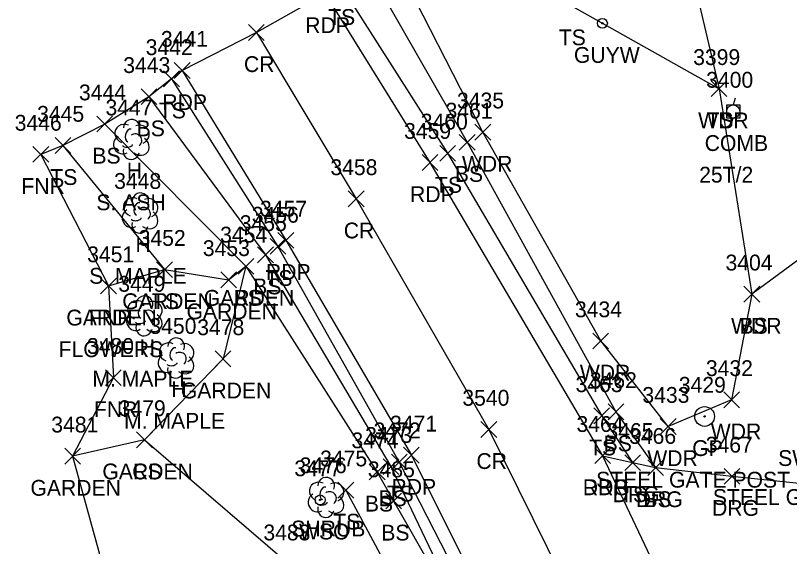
# Model space of a CAD drawing. Extents: x 1461855 to 1464118, y 556196 to 557441.
# Drawn here: x 1461854.8 to 1461952.7, y 556656.2 to 556723.3 of the extents above; entities that cross this region are included whole.
import ezdxf

# ---------------------------------------------------------------- set-up
doc = ezdxf.new("R2010")
doc.units = 0
for name, color, linetype in [('L_A', 7, 'Continuous'), ('L_C', 7, 'Continuous'), ('L_I', 7, 'Continuous'), ('L_TIC', 7, 'Continuous'), ('LAPB', 7, 'Continuous'), ('LAWA', 7, 'Continuous'), ('LELB', 7, 'Continuous'), ('LFNC', 7, 'Continuous'), ('LSH', 7, 'Continuous'), ('LSOGP', 7, 'Continuous'), ('LTD', 7, 'Continuous'), ('P_A', 7, 'Continuous'), ('P_I', 7, 'Continuous'), ('P_TIC', 7, 'Continuous'), ('PET', 7, 'Continuous'), ('PRC', 7, 'Continuous'), ('R_A', 7, 'Continuous'), ('R_C', 7, 'Continuous'), ('R_I', 7, 'Continuous'), ('R_TIC', 7, 'Continuous'), ('RDG', 7, 'Continuous'), ('RGP', 7, 'Continuous'), ('U_A', 7, 'Continuous'), ('U_C', 7, 'Continuous'), ('U_I', 7, 'Continuous'), ('UP', 7, 'Continuous'), ('UPGW', 7, 'Continuous'), ('UWV', 7, 'Continuous')]:
    doc.layers.add(name, color=color, linetype=linetype)

msp = doc.modelspace()

# ---------------------------------------------------------------- linework, layer by layer
at = {"layer": 'L_TIC'}
for points in [[(1461873.548, 556714.325), (1461875.548, 556716.325)], [(1461875.548, 556714.325), (1461873.548, 556716.325)], [(1461942.815, 556713.07), (1461944.815, 556715.07)], [(1461944.815, 556713.07), (1461942.815, 556715.07)], [(1461942.815, 556713.07), (1461944.815, 556715.07)], [(1461944.815, 556713.07), (1461942.815, 556715.07)], [(1461870.708, 556712.061), (1461872.708, 556714.061)], [(1461872.708, 556712.061), (1461870.708, 556714.061)], [(1461865.11, 556708.605), (1461867.11, 556710.605)], [(1461867.11, 556708.605), (1461865.11, 556710.605)], [(1461912.933, 556707.582), (1461914.933, 556709.582)], [(1461914.933, 556707.582), (1461912.933, 556709.582)], [(1461859.82, 556705.9), (1461861.82, 556707.9)], [(1461861.82, 556705.9), (1461859.82, 556707.9)], [(1461910.96, 556706.296), (1461912.96, 556708.296)], [(1461912.96, 556706.296), (1461910.96, 556708.296)], [(1461908.481, 556704.911), (1461910.481, 556706.911)], [(1461910.481, 556704.911), (1461908.481, 556706.911)], [(1461857.034, 556704.764), (1461859.034, 556706.764)], [(1461859.034, 556704.764), (1461857.034, 556706.764)], [(1461887.028, 556693.129), (1461889.028, 556695.129)], [(1461889.028, 556693.129), (1461887.028, 556695.129)], [(1461885.45, 556692.067), (1461887.45, 556694.067)], [(1461887.45, 556692.067), (1461885.45, 556694.067)], [(1461882.97, 556690.62), (1461884.97, 556692.62)], [(1461884.97, 556690.62), (1461882.97, 556692.62)], [(1461882.97, 556690.62), (1461884.97, 556692.62)], [(1461884.97, 556690.62), (1461882.97, 556692.62)], [(1461872.663, 556690.196), (1461874.663, 556692.196)], [(1461874.663, 556690.196), (1461872.663, 556692.196)], [(1461872.663, 556690.196), (1461874.663, 556692.196)], [(1461874.663, 556690.196), (1461872.663, 556692.196)], [(1461880.78, 556688.911), (1461882.78, 556690.911)], [(1461882.78, 556688.911), (1461880.78, 556690.911)], [(1461865.582, 556688.127), (1461867.582, 556690.127)], [(1461867.582, 556688.127), (1461865.582, 556690.127)], [(1461865.582, 556688.127), (1461867.582, 556690.127)], [(1461867.582, 556688.127), (1461865.582, 556690.127)], [(1461946.975, 556687.088), (1461948.975, 556689.088)], [(1461948.975, 556687.088), (1461946.975, 556689.088)], [(1461946.975, 556687.088), (1461948.975, 556689.088)], [(1461948.975, 556687.088), (1461946.975, 556689.088)], [(1461927.85, 556681.169), (1461929.85, 556683.169)], [(1461929.85, 556681.169), (1461927.85, 556683.169)], [(1461880.073, 556678.905), (1461882.073, 556680.905)], [(1461882.073, 556678.905), (1461880.073, 556680.905)], [(1461866.209, 556676.536), (1461868.209, 556678.536)], [(1461868.209, 556676.536), (1461866.209, 556678.536)], [(1461944.413, 556673.732), (1461946.413, 556675.732)], [(1461946.413, 556673.732), (1461944.413, 556675.732)], [(1461927.974, 556671.704), (1461929.974, 556673.704)], [(1461929.974, 556671.704), (1461927.974, 556673.704)], [(1461929.781, 556672.211), (1461931.781, 556674.211)], [(1461931.781, 556672.211), (1461929.781, 556674.211)], [(1461936.382, 556670.345), (1461938.382, 556672.345)], [(1461938.382, 556670.345), (1461936.382, 556672.345)], [(1461870.14, 556668.665), (1461872.14, 556670.665)], [(1461872.14, 556668.665), (1461870.14, 556670.665)], [(1461870.14, 556668.665), (1461872.14, 556670.665)], [(1461872.14, 556668.665), (1461870.14, 556670.665)], [(1461861.044, 556666.595), (1461863.044, 556668.595)], [(1461863.044, 556666.595), (1461861.044, 556668.595)], [(1461902.375, 556665.86), (1461904.375, 556667.86)], [(1461904.375, 556665.86), (1461902.375, 556667.86)], [(1461931.884, 556665.779), (1461933.884, 556667.779)], [(1461933.884, 556665.779), (1461931.884, 556667.779)], [(1461901.311, 556665.277), (1461903.311, 556667.277)], [(1461903.311, 556665.277), (1461901.311, 556667.277)], [(1461934.802, 556665.155), (1461936.802, 556667.155)], [(1461936.802, 556665.155), (1461934.802, 556667.155)], [(1461899.579, 556664.598), (1461901.579, 556666.598)], [(1461901.579, 556664.598), (1461899.579, 556666.598)], [(1461895.617, 556662.31), (1461897.617, 556664.31)], [(1461897.617, 556662.31), (1461895.617, 556664.31)], [(1461901.653, 556660.933), (1461903.653, 556662.933)], [(1461903.653, 556660.933), (1461901.653, 556662.933)]]:
    msp.add_lwpolyline(points, dxfattribs=at)
at = {"layer": 'LAPB'}
msp.add_lwpolyline([(1461866.582, 556689.127), (1461873.663, 556691.196), (1461881.78, 556689.911), (1461883.97, 556691.62), (1461881.073, 556679.905), (1461871.14, 556669.665), (1461862.044, 556667.595)], dxfattribs=at)
at = {"layer": 'LAWA'}
msp.add_lwpolyline([(1461926.987, 556765.992), (1461932.919, 556746.538), (1461939.159, 556733.989), (1461943.815, 556714.07), (1461947.975, 556688.088), (1461945.413, 556674.732), (1461937.382, 556671.345), (1461928.85, 556682.169), (1461913.933, 556708.582), (1461902.601, 556730.777)], dxfattribs=at)
at = {"layer": 'LELB'}
for points in [[(1461981.863, 556780.657), (1461976.053, 556771.1), (1461967.284, 556761.909), (1461962.875, 556749.079), (1461964.986, 556728.538), (1461974.133, 556719.419), (1461960.957, 556697.669), (1461947.975, 556688.088)], [(1461918.83, 556747.056), (1461925.141, 556724.567), (1461943.815, 556714.07)], [(1461899.554, 556729), (1461911.96, 556707.296), (1461930.781, 556673.211), (1461935.802, 556666.155)], [(1461895.967, 556727.144), (1461909.481, 556705.911), (1461928.974, 556672.704), (1461932.884, 556666.779)], [(1461874.548, 556715.325), (1461888.028, 556694.129), (1461903.375, 556666.86), (1461916.457, 556641.264)], [(1461871.708, 556713.061), (1461886.45, 556693.067), (1461902.311, 556666.277), (1461913.17, 556643.486), (1461914.66, 556633.875), (1461909.849, 556627.641), (1461892.006, 556624.846)], [(1461866.11, 556709.605), (1461883.97, 556691.62), (1461900.579, 556665.598), (1461902.653, 556661.933), (1461913.17, 556643.486)], [(1461860.82, 556706.9), (1461873.663, 556691.196)], [(1461871.14, 556669.665), (1461889.442, 556653.951), (1461903.994, 556630.304)], [(1461896.617, 556663.31), (1461909.993, 556638.365), (1461903.994, 556630.304), (1461885.956, 556629.023), (1461872.959, 556631.814)]]:
    msp.add_lwpolyline(points, dxfattribs=at)
at = {"layer": 'LFNC'}
msp.add_lwpolyline([(1461858.034, 556705.764), (1461866.582, 556689.127), (1461867.209, 556677.536)], dxfattribs=at)
at = {"layer": 'LSH'}
msp.add_line((1461894.083, 556662.444), (1461894.083, 556662.444), dxfattribs=at)
msp.add_line((1461894.083, 556662.444), (1461894.083, 556662.444), dxfattribs=at)
msp.add_arc((1461894.129, 556663.878), 1.047, 335.52715, 180.95627, dxfattribs=at)
for centre, major_axis, ratio, start_param, end_param in [((1461893.291, 556663.111), (1.21, -0.512), 0.895232, 1.570796, 4.712389), ((1461895.124, 556663.028), (-1.141, -0.483), 0.949671, 1.570796, 4.712389), ((1461893.874, 556662.903), (-0.208, -0.792), 0.645439, 3.141593, 6.283185), ((1461894.583, 556662.278), (-0.5, 0.667), 0.989748, 3.141593, 6.283185), ((1461892.999, 556661.736), (0.584, -1.042), 0.959034, 3.141593, 6.283185), ((1461895.083, 556661.611), (-1.09, 0.792), 0.841452, 1.570796, 4.712389), ((1461894.083, 556660.944), (0.265, 1.061), 0.942809, 1.570796, 4.712389), ((1461893.624, 556661.694), (-0.625, -0.083), 0.423636, 0, 3.141593)]:
    msp.add_ellipse(centre, major_axis=major_axis, ratio=ratio, start_param=start_param, end_param=end_param, dxfattribs=at)
at = {"layer": 'LSOGP'}
msp.add_lwpolyline([(1461963.066, 556782.587), (1461946.843, 556774.323), (1461926.987, 556765.992), (1461918.83, 556747.056), (1461902.601, 556730.777), (1461899.554, 556729), (1461895.967, 556727.144), (1461893.981, 556726.102), (1461885.29, 556721.181), (1461875.912, 556716.37), (1461874.548, 556715.325), (1461871.708, 556713.061), (1461866.11, 556709.605), (1461860.82, 556706.9), (1461858.034, 556705.764), (1461866.582, 556689.127), (1461867.209, 556677.536), (1461862.044, 556667.595), (1461868.287, 556644.972), (1461872.959, 556631.814), (1461870.489, 556624.544), (1461869.707, 556611.539)], dxfattribs=at)
at = {"layer": 'LTD'}
for p, q in [((1461869.465, 556707.704), (1461869.465, 556707.704)), ((1461869.465, 556707.704), (1461869.465, 556707.704)), ((1461870.564, 556698.408), (1461870.564, 556698.408)), ((1461870.564, 556698.408), (1461870.564, 556698.408)), ((1461871.096, 556685.396), (1461871.096, 556685.396)), ((1461871.096, 556685.396), (1461871.096, 556685.396)), ((1461875.106, 556680.069), (1461875.106, 556680.069)), ((1461875.106, 556680.069), (1461875.106, 556680.069))]:
    msp.add_line(p, q, dxfattribs=at)
for centre in [(1461869.512, 556709.138), (1461870.611, 556699.842), (1461871.143, 556686.83), (1461875.153, 556681.503)]:
    msp.add_arc(centre, 1.047, 335.52715, 180.95627, dxfattribs=at)
for centre, major_axis, ratio, start_param, end_param in [((1461868.674, 556708.37), (1.21, -0.512), 0.895232, 1.570796, 4.712389), ((1461869.257, 556708.162), (-0.208, -0.792), 0.645439, 3.141593, 6.283185), ((1461870.507, 556708.287), (-1.141, -0.483), 0.949671, 1.570796, 4.712389), ((1461868.382, 556706.995), (0.584, -1.042), 0.959034, 3.141593, 6.283185), ((1461869.965, 556707.537), (-0.5, 0.667), 0.989748, 3.141593, 6.283185), ((1461869.007, 556706.954), (-0.625, -0.083), 0.423636, 0, 3.141593), ((1461870.466, 556706.87), (-1.09, 0.792), 0.841452, 1.570796, 4.712389), ((1461869.466, 556706.204), (0.265, 1.061), 0.942809, 1.570796, 4.712389), ((1461869.772, 556699.074), (1.21, -0.512), 0.895232, 1.570796, 4.712389), ((1461871.605, 556698.991), (-1.141, -0.483), 0.949671, 1.570796, 4.712389), ((1461870.355, 556698.866), (-0.208, -0.792), 0.645439, 3.141593, 6.283185), ((1461871.064, 556698.241), (-0.5, 0.667), 0.989748, 3.141593, 6.283185), ((1461869.481, 556697.699), (0.584, -1.042), 0.959034, 3.141593, 6.283185), ((1461871.564, 556697.575), (-1.09, 0.792), 0.841452, 1.570796, 4.712389), ((1461870.564, 556696.908), (0.265, 1.061), 0.942809, 1.570796, 4.712389), ((1461870.106, 556697.658), (-0.625, -0.083), 0.423636, 0, 3.141593), ((1461870.304, 556686.063), (1.21, -0.512), 0.895232, 1.570796, 4.712389), ((1461872.138, 556685.98), (-1.141, -0.483), 0.949671, 1.570796, 4.712389), ((1461870.888, 556685.855), (-0.208, -0.792), 0.645439, 3.141593, 6.283185), ((1461870.013, 556684.688), (0.584, -1.042), 0.959034, 3.141593, 6.283185), ((1461871.596, 556685.23), (-0.5, 0.667), 0.989748, 3.141593, 6.283185), ((1461872.096, 556684.563), (-1.09, 0.792), 0.841452, 1.570796, 4.712389), ((1461870.638, 556684.646), (-0.625, -0.083), 0.423636, 0, 3.141593), ((1461871.096, 556683.896), (0.265, 1.061), 0.942809, 1.570796, 4.712389), ((1461874.314, 556680.736), (1.21, -0.512), 0.895232, 1.570796, 4.712389), ((1461876.148, 556680.653), (-1.141, -0.483), 0.949671, 1.570796, 4.712389), ((1461874.898, 556680.528), (-0.208, -0.792), 0.645439, 3.141593, 6.283185), ((1461875.606, 556679.903), (-0.5, 0.667), 0.989748, 3.141593, 6.283185), ((1461874.023, 556679.361), (0.584, -1.042), 0.959034, 3.141593, 6.283185), ((1461876.106, 556679.236), (-1.09, 0.792), 0.841452, 1.570796, 4.712389), ((1461875.106, 556678.569), (0.265, 1.061), 0.942809, 1.570796, 4.712389), ((1461874.648, 556679.319), (-0.625, -0.083), 0.423636, 0, 3.141593)]:
    msp.add_ellipse(centre, major_axis=major_axis, ratio=ratio, start_param=start_param, end_param=end_param, dxfattribs=at)
at = {"layer": 'P_TIC'}
for points in [[(1461884.29, 556720.181), (1461886.29, 556722.181)], [(1461886.29, 556720.181), (1461884.29, 556722.181)], [(1461874.912, 556715.37), (1461876.912, 556717.37)], [(1461876.912, 556715.37), (1461874.912, 556717.37)], [(1461906.245, 556703.732), (1461908.245, 556705.732)], [(1461908.245, 556703.732), (1461906.245, 556705.732)], [(1461896.917, 556699.144), (1461898.917, 556701.144)], [(1461898.917, 556699.144), (1461896.917, 556701.144)], [(1461888.015, 556693.898), (1461890.015, 556695.898)], [(1461890.015, 556693.898), (1461888.015, 556695.898)], [(1461913.696, 556669.981), (1461915.696, 556671.981)], [(1461915.696, 556669.981), (1461913.696, 556671.981)], [(1461903.899, 556666.719), (1461905.899, 556668.719)], [(1461905.899, 556666.719), (1461903.899, 556668.719)], [(1461928.095, 556666.663), (1461930.095, 556668.663)], [(1461930.095, 556666.663), (1461928.095, 556668.663)]]:
    msp.add_lwpolyline(points, dxfattribs=at)
at = {"layer": 'PET'}
for points in [[(1461893.981, 556726.102), (1461907.245, 556704.732), (1461929.095, 556667.663), (1461940.035, 556644.486)], [(1461875.912, 556716.37), (1461889.015, 556694.898), (1461904.899, 556667.719), (1461916.311, 556644.935)]]:
    msp.add_lwpolyline(points, dxfattribs=at)
at = {"layer": 'PRC'}
msp.add_lwpolyline([(1461885.29, 556721.181), (1461897.917, 556700.144), (1461914.696, 556670.981), (1461929.486, 556641.056)], dxfattribs=at)
at = {"layer": 'R_TIC'}
for points in [[(1461928.095, 556666.663), (1461930.095, 556668.663)], [(1461930.095, 556666.663), (1461928.095, 556668.663)], [(1461931.884, 556665.779), (1461933.884, 556667.779)], [(1461933.884, 556665.779), (1461931.884, 556667.779)], [(1461934.802, 556665.155), (1461936.802, 556667.155)], [(1461936.802, 556665.155), (1461934.802, 556667.155)], [(1461944.448, 556664.055), (1461946.448, 556666.055)], [(1461946.448, 556664.055), (1461944.448, 556666.055)]]:
    msp.add_lwpolyline(points, dxfattribs=at)
at = {"layer": 'RDG'}
msp.add_lwpolyline([(1461929.095, 556667.663), (1461932.884, 556666.779), (1461935.802, 556666.155), (1461945.448, 556665.055), (1461957.989, 556663.765), (1461957.162, 556653.392)], dxfattribs=at)
at = {"layer": 'RGP'}
msp.add_line((1461941.998, 556672.622), (1461941.998, 556672.622), dxfattribs=at)
for radius in [1.25, 0.0833]:
    msp.add_circle((1461941.998, 556672.622), radius, dxfattribs=at)
at = {"layer": 'UP'}
for p, q in [((1461945.868, 556712.866), (1461945.618, 556712.033)), ((1461944.784, 556710.366), (1461944.784, 556712.033)), ((1461944.784, 556712.033), (1461946.451, 556712.033)), ((1461946.451, 556712.033), (1461946.451, 556710.366)), ((1461945.618, 556711.199), (1461945.618, 556711.199)), ((1461946.451, 556710.366), (1461944.784, 556710.366)), ((1461945.368, 556709.533), (1461945.618, 556710.366))]:
    msp.add_line(p, q, dxfattribs=at)
msp.add_circle((1461945.618, 556711.199), 0.833, dxfattribs=at)
at = {"layer": 'UPGW'}
for radius in [0.625, 0.0833]:
    msp.add_circle((1461929.069, 556722.343), radius, dxfattribs=at)
at = {"layer": 'UWV'}
for radius in [0.625, 0.0833]:
    msp.add_circle((1461893.358, 556662.067), radius, dxfattribs=at)

# ---------------------------------------------------------------- texts
at = {"layer": 'L_A'}
for s, p in [('TS', (1461894.376, 556722.144)), ('TS', (1461923.55, 556719.567)), ('TS', (1461872.957, 556710.325)), ('WDR', (1461941.177, 556709.07)), ('TS', (1461942.225, 556709.07)), ('BS', (1461870.149, 556708.061)), ('BS', (1461864.551, 556704.605)), ('WDR', (1461911.295, 556703.582)), ('H', (1461868.899, 556702.704)), ('BS', (1461910.401, 556702.296)), ('TS', (1461859.23, 556701.9)), ('FNR', (1461855.569, 556700.764)), ('TS', (1461907.89, 556700.911)), ('H', (1461869.997, 556693.408)), ('TS', (1461886.438, 556689.129)), ('BS', (1461884.891, 556688.067)), ('GARDEN', (1461878.64, 556686.62)), ('BS', (1461882.411, 556686.62)), ('GARDEN', (1461868.332, 556686.196)), ('TS', (1461872.072, 556686.196)), ('GARDEN', (1461876.449, 556684.911)), ('GARDEN', (1461861.252, 556684.127)), ('FNR', (1461864.118, 556684.127)), ('WDR', (1461945.338, 556683.088)), ('BS', (1461946.416, 556683.088)), ('H', (1461870.529, 556680.396)), ('WDR', (1461926.212, 556677.169)), ('H', (1461874.539, 556675.069)), ('GARDEN', (1461875.742, 556674.905)), ('FNR', (1461864.745, 556672.536)), ('WDR', (1461942.776, 556669.732)), ('TS', (1461927.383, 556667.704)), ('BS', (1461929.221, 556668.211)), ('WDR', (1461934.744, 556666.345)), ('GARDEN', (1461865.81, 556664.665)), ('CS', (1461869.581, 556664.665)), ('GARDEN', (1461856.713, 556662.595)), ('TS', (1461901.784, 556661.86)), ('BS', (1461900.752, 556661.277)), ('TS', (1461931.294, 556661.779)), ('BS', (1461934.243, 556661.155)), ('BS', (1461899.02, 556660.598)), ('TS', (1461895.027, 556658.31)), ('SHRUB', (1461889.713, 556657.444)), ('BS', (1461901.094, 556656.933))]:
    msp.add_text(s, height=2, dxfattribs=at).set_placement(p)
at = {"layer": 'L_C'}
for s, p in [('S. ASH', (1461865.056, 556698.704)), ('S. MAPLE', (1461864.139, 556689.408)), ('FLOWERS', (1461860.283, 556680.127)), ('M. MAPLE', (1461864.545, 556676.396)), ('M. MAPLE', (1461868.555, 556671.069))]:
    msp.add_text(s, height=2, dxfattribs=at).set_placement(p)
at = {"layer": 'L_I'}
for s, p in [('3442', (1461871.288, 556718.325)), ('3399', (1461940.548, 556717.07)), ('3399', (1461940.548, 556717.07)), ('3443', (1461868.449, 556716.061)), ('3444', (1461862.85, 556712.605)), ('3435', (1461910.673, 556711.582)), ('3445', (1461857.56, 556709.9)), ('3447', (1461866.206, 556710.704)), ('3461', (1461909.22, 556710.296)), ('3460', (1461906.087, 556708.911)), ('3446', (1461854.719, 556708.764)), ('3448', (1461867.304, 556701.408)), ('3456', (1461884.713, 556697.129)), ('3455', (1461883.19, 556696.067)), ('3452', (1461870.403, 556694.196)), ('3452', (1461870.403, 556694.196)), ('3454', (1461880.711, 556694.62)), ('3454', (1461880.711, 556694.62)), ('3453', (1461878.52, 556692.911)), ('3451', (1461863.89, 556692.127)), ('3451', (1461863.89, 556692.127)), ('3404', (1461944.637, 556691.088)), ('3404', (1461944.637, 556691.088)), ('3449', (1461867.828, 556688.396)), ('3434', (1461925.59, 556685.169)), ('3450', (1461871.76, 556683.069)), ('3478', (1461877.813, 556682.905)), ('3480', (1461863.863, 556680.536)), ('3432', (1461942.154, 556677.732)), ('3463', (1461925.667, 556675.704)), ('3462', (1461927.473, 556676.211)), ('3433', (1461934.122, 556674.345)), ('3479', (1461867.873, 556672.665)), ('3479', (1461867.873, 556672.665)), ('3481', (1461859.351, 556670.595)), ('3472', (1461900.115, 556669.86)), ('3465', (1461929.577, 556669.779)), ('3473', (1461899.052, 556669.277)), ('3466', (1461932.44, 556669.155)), ('3474', (1461897.319, 556668.598)), ('3475', (1461893.357, 556666.31)), ('3476', (1461890.768, 556665.444)), ('3485', (1461899.393, 556664.933)), ('3483', (1461886.182, 556656.951))]:
    msp.add_text(s, height=2, dxfattribs=at).set_placement(p)
at = {"layer": 'P_A'}
for s, p in [('RDP', (1461891.469, 556721.102)), ('CR', (1461883.723, 556716.181)), ('RDP', (1461873.4, 556711.37)), ('RDP', (1461904.733, 556699.732)), ('CR', (1461896.35, 556695.144)), ('RDP', (1461886.503, 556689.898)), ('CR', (1461913.129, 556665.981)), ('RDP', (1461902.387, 556662.719)), ('RDP', (1461926.583, 556662.663))]:
    msp.add_text(s, height=2, dxfattribs=at).set_placement(p)
at = {"layer": 'P_I'}
for s, p in [('3441', (1461873.219, 556719.37)), ('3459', (1461903.977, 556707.732)), ('3458', (1461894.657, 556703.144)), ('3457', (1461885.755, 556697.898)), ('3540', (1461911.349, 556673.981)), ('3471', (1461902.206, 556670.719)), ('3464', (1461925.787, 556670.663))]:
    msp.add_text(s, height=2, dxfattribs=at).set_placement(p)
at = {"layer": 'R_A'}
for s, p in [('GP', (1461940.431, 556667.622)), ('SWS ST', (1461951.298, 556666.361)), ('DRG', (1461926.583, 556662.663)), ('DRG', (1461930.372, 556661.779)), ('DRG', (1461933.29, 556661.155)), ('DRG', (1461942.936, 556660.055))]:
    msp.add_text(s, height=2, dxfattribs=at).set_placement(p)
at = {"layer": 'R_C'}
for p in [(1461928.274, 556663.622), (1461943.034, 556661.43)]:
    msp.add_text('STEEL GATE POST', height=2, dxfattribs=at).set_placement(p)
at = {"layer": 'R_I'}
for s, p in [('3429', (1461938.73, 556675.622)), ('3464', (1461925.787, 556670.663)), ('3465', (1461929.577, 556669.779)), ('3466', (1461932.44, 556669.155)), ('3467', (1461942.14, 556668.055))]:
    msp.add_text(s, height=2, dxfattribs=at).set_placement(p)
at = {"layer": 'U_A'}
for s, p in [('GUYW', (1461925.463, 556717.343)), ('COMB', (1461942.003, 556706.199)), ('WSO', (1461890.689, 556657.067))]:
    msp.add_text(s, height=2, dxfattribs=at).set_placement(p)
at = {"layer": 'U_C'}
msp.add_text('25T/2', height=2, dxfattribs=at).set_placement((1461941.303, 556702.199))
at = {"layer": 'U_I'}
for s, p in [('3400', (1461942.192, 556714.199)), ('3477', (1461890.098, 556665.067))]:
    msp.add_text(s, height=2, dxfattribs=at).set_placement(p)

doc.saveas('drawing.dxf')
